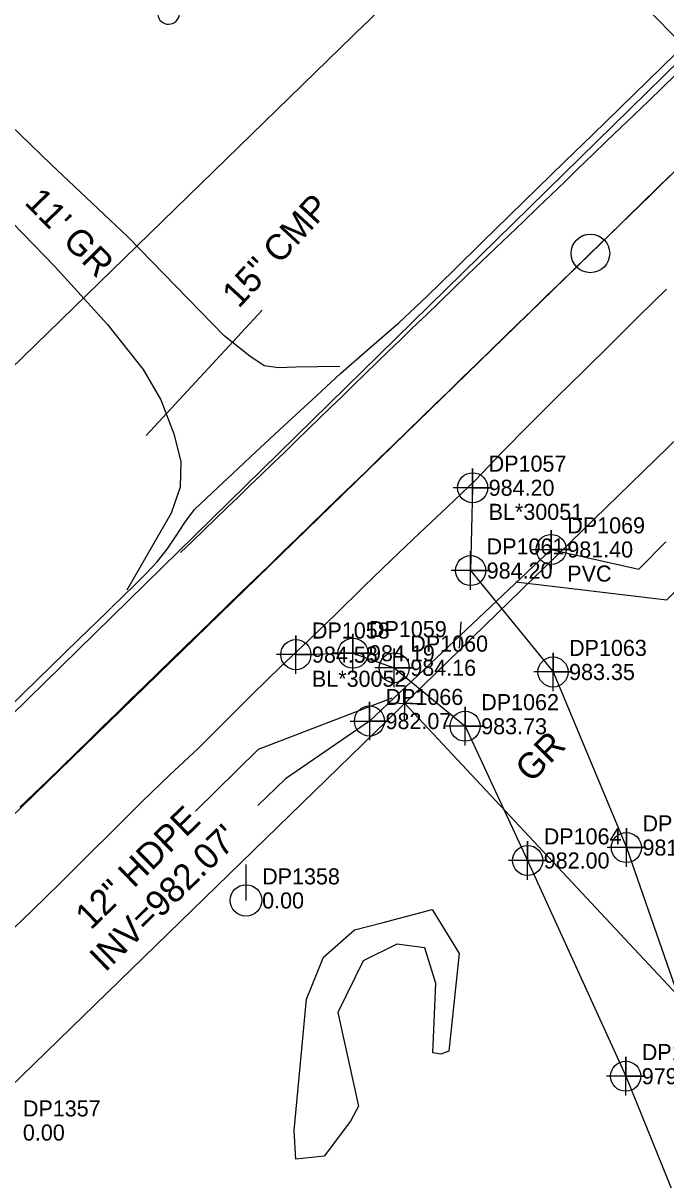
# Model space of a CAD drawing. Extents: x 1182322 to 1186765, y 572295 to 575411.
# Drawn here: x 1184975.7 to 1185075.6, y 574526.7 to 574706.6 of the extents above; entities that cross this region are included whole.
import ezdxf

# ---------------------------------------------------------------- set-up
doc = ezdxf.new("R2010")
doc.units = 0
for name, color, linetype in [('COGO Default Chain', 7, 'Continuous'), ('Exist Horizontal Alignment', 7, 'Continuous'), ('Exist Horizontal Alignment Point', 7, 'Continuous'), ('Exist Property Corner CELL', 7, 'Continuous'), ('Exist Property Line', 7, 'Continuous'), ('Exist Right of Way Line', 7, 'Continuous'), ('Exist Right of Way Width CELL', 7, 'Continuous'), ('Exist Roads EOP', 7, 'Continuous'), ('Exist Roads EOT', 7, 'Continuous'), ('Exist Roads Soil', 7, 'Continuous'), ('Exist Roads Soil Cogo Comment', 7, 'Continuous'), ('Exist Roads Soil Cogo Elevation', 7, 'Continuous'), ('Exist Roads Soil Cogo Number', 7, 'Continuous'), ('Exist Roads Soil Cogo Point CELL', 7, 'Continuous'), ('Exist Roads Soil Text', 7, 'Continuous'), ('Exist Structure Minor Pipes CMP 15 Inch', 7, 'Continuous'), ('Exist Structure Minor Pipes CMP 15 Inch Text', 7, 'Continuous'), ('Exist Structure Minor Pipes HDPE 12 Inch', 7, 'Continuous'), ('Exist Structure Minor Pipes HDPE 12 Inch Cogo Comment', 7, 'Continuous'), ('Exist Structure Minor Pipes HDPE 12 Inch Cogo Elevation', 7, 'Continuous'), ('Exist Structure Minor Pipes HDPE 12 Inch Cogo Number', 7, 'Continuous'), ('Exist Structure Minor Pipes HDPE 12 Inch Cogo Point CELL', 7, 'Continuous'), ('Exist Structure Minor Pipes HDPE 12 Inch Invert', 7, 'Continuous'), ('Exist Structure Minor Pipes HDPE 12 Inch Text', 7, 'Continuous'), ('Exist Structure Minor Pipes RCP 24 Inch Invert', 7, 'Continuous'), ('Exist Utilities Power Pole CELL', 7, 'Continuous'), ('Exist Utilities Power Pole Cogo Elevation', 7, 'Continuous'), ('Exist Utilities Power Pole Cogo Number', 7, 'Continuous'), ('Exist Utilities Water UG Line SUE LOS C', 7, 'Continuous'), ('Exist Vegetation Tree CELL', 7, 'Continuous'), ('Exist Vegetation Woods Line', 7, 'Continuous')]:
    doc.layers.add(name, color=color, linetype=linetype)

msp = doc.modelspace()

# ---------------------------------------------------------------- linework, layer by layer
at = {"layer": 'COGO Default Chain'}
msp.add_line((1184906.77, 574517.85), (1185063.9, 574670.82), dxfattribs=at)
msp.add_arc((1211496.85, 547519.36), 37893.3, 134.022628, 134.231777, dxfattribs=at)
at = {"layer": 'Exist Horizontal Alignment'}
msp.add_line((1184906.77, 574517.85), (1185063.9, 574670.82), dxfattribs=at)
msp.add_arc((1211496.85, 547519.36), 37893.3, 134.022628, 134.231777, dxfattribs=at)
at = {"layer": 'Exist Horizontal Alignment Point'}
msp.add_circle((1185063.9, 574670.82), 3, dxfattribs=at)
at = {"layer": 'Exist Property Corner CELL'}
msp.add_line((1185035.03, 574600.84), (1185035.03, 574600.84), dxfattribs=at)
msp.add_lwpolyline([(1185032.53, 574600.92), (1185037.53, 574600.75), (1185035.03, 574600.84), (1185035.11, 574603.34), (1185034.94, 574598.34)], dxfattribs=at)
at = {"layer": 'Exist Property Line'}
msp.add_line((1185035.03, 574600.84), (1185095.5, 574536.04), dxfattribs=at)
at = {"layer": 'Exist Right of Way Line'}
for p, q in [((1184871.9, 574553.67), (1185029.02, 574706.64)), ((1184927.7, 574496.35), (1185084.83, 574649.32))]:
    msp.add_line(p, q, dxfattribs=at)
msp.add_arc((1211496.85, 547519.36), 37943.3, 134.022628, 134.231777, dxfattribs=at)
at = {"layer": 'Exist Right of Way Width CELL'}
msp.add_line((1185087.47, 574693.74), (1185065.48, 574716.36), dxfattribs=at)
at = {"layer": 'Exist Roads EOP'}
for points in [[(1185007.48, 574635.8), (1185011.87, 574639.89), (1185016.26, 574643.98), (1185020.65, 574648.07), (1185025.06, 574652.14), (1185029.56, 574656.1), (1185034.11, 574660.02), (1185038.5, 574664.11), (1185042.79, 574668.3), (1185047.04, 574672.53), (1185051.32, 574676.73), (1185055.62, 574680.92), (1185059.92, 574685.1), (1185064.22, 574689.29), (1185068.51, 574693.48), (1185072.81, 574697.66), (1185077.11, 574701.85)], [(1185075.72, 574665.26), (1185071.45, 574661.05), (1185067.18, 574656.83), (1185062.91, 574652.62), (1185058.64, 574648.4), (1185054.38, 574644.18), (1185050.19, 574639.89), (1185046.03, 574635.56), (1185041.7, 574631.41), (1185037.34, 574627.29), (1185032.97, 574623.18), (1185028.66, 574619.01), (1185024.41, 574614.77), (1185020.06, 574610.63), (1185015.72, 574606.49), (1185011.43, 574602.3), (1185007.18, 574598.06), (1185002.93, 574593.83), (1184998.55, 574589.73), (1184994.24, 574585.55), (1184989.99, 574581.33), (1184985.73, 574577.1), (1184981.48, 574572.86), (1184977.18, 574568.68), (1184972.87, 574564.5)], [(1184989.5, 574615.78), (1184991.29, 574617.52), (1184993.08, 574619.27), (1184994.87, 574621.01), (1184996.58, 574622.84), (1184998.1, 574624.82), (1184999.54, 574626.87), (1185000.85, 574628.99), (1185002.35, 574631), (1185004.17, 574632.71), (1185006, 574634.41), (1185007.48, 574635.8)], [(1184893.98, 574523.02), (1184898.26, 574527.23), (1184902.55, 574531.42), (1184906.85, 574535.61), (1184911.15, 574539.79), (1184915.45, 574543.98), (1184919.74, 574548.16), (1184924.05, 574552.34), (1184928.36, 574556.52), (1184932.67, 574560.69), (1184936.97, 574564.87), (1184941.28, 574569.04), (1184945.61, 574573.2), (1184949.94, 574577.35), (1184954.28, 574581.5), (1184958.61, 574585.65), (1184962.92, 574589.83), (1184967.19, 574594.03), (1184971.47, 574598.24), (1184975.77, 574602.43), (1184980.07, 574606.61), (1184984.37, 574610.8), (1184988.67, 574614.98), (1184989.48, 574615.76)]]:
    msp.add_lwpolyline(points, dxfattribs=at)
at = {"layer": 'Exist Roads EOT'}
for points in [[(1185038.35, 574661.22), (1185040.5, 574663.31), (1185042.66, 574665.4), (1185044.81, 574667.48), (1185046.98, 574669.55), (1185049.16, 574671.62), (1185051.33, 574673.69), (1185053.49, 574675.77), (1185055.65, 574677.85), (1185057.81, 574679.93), (1185059.97, 574682.02), (1185062.12, 574684.11), (1185064.26, 574686.21), (1185066.42, 574688.29), (1185068.58, 574690.37), (1185070.75, 574692.44), (1185072.92, 574694.52), (1185075.08, 574696.6), (1185077.24, 574698.68)], [(1185076.31, 574682.96), (1185074.17, 574680.86), (1185072.02, 574678.76), (1185069.88, 574676.66), (1185067.74, 574674.56), (1185065.59, 574672.47), (1185063.44, 574670.38), (1185061.29, 574668.29), (1185059.13, 574666.2), (1185056.98, 574664.11), (1185054.83, 574662.02), (1185052.68, 574659.93), (1185050.53, 574657.83), (1185048.39, 574655.74), (1185046.24, 574653.65), (1185044.09, 574651.55), (1185041.94, 574649.46), (1185039.79, 574647.37), (1185037.64, 574645.28), (1185035.49, 574643.19), (1185033.33, 574641.1), (1185031.18, 574639.01), (1185029.03, 574636.92), (1185026.87, 574634.83), (1185024.72, 574632.74), (1185022.57, 574630.65), (1185020.42, 574628.57), (1185018.26, 574626.48), (1185016.11, 574624.39), (1185013.95, 574622.3), (1185011.8, 574620.21), (1185009.64, 574618.13), (1185007.49, 574616.04), (1185005.33, 574613.95), (1185003.18, 574611.87), (1185001.02, 574609.78), (1184998.87, 574607.69), (1184996.72, 574605.6), (1184994.57, 574603.51), (1184992.42, 574601.41), (1184990.28, 574599.31), (1184988.14, 574597.21), (1184986, 574595.11), (1184983.85, 574593.02), (1184981.7, 574590.93), (1184979.55, 574588.84), (1184977.39, 574586.75), (1184975.24, 574584.66)], [(1185000.2, 574624.29), (1185002.01, 574626.02), (1185003.8, 574627.76), (1185005.6, 574629.5), (1185007.39, 574631.24), (1185009.19, 574632.98), (1185010.99, 574634.71), (1185012.79, 574636.45), (1185014.59, 574638.18), (1185016.38, 574639.92), (1185018.18, 574641.66), (1185019.97, 574643.41), (1185021.76, 574645.15), (1185023.55, 574646.89), (1185025.35, 574648.64), (1185027.14, 574650.38), (1185028.93, 574652.12), (1185030.72, 574653.86), (1185032.52, 574655.6), (1185034.32, 574657.33), (1185036.12, 574659.07), (1185037.92, 574660.81), (1185038.35, 574661.22)]]:
    msp.add_lwpolyline(points, dxfattribs=at)
at = {"layer": 'Exist Roads Soil'}
for points in [[(1184864.18, 574782.1), (1184871.91, 574781.1), (1184874.14, 574780.41), (1184878.92, 574775.51), (1184891.68, 574760.82), (1184894.88, 574763.09), (1184906.71, 574747.55), (1184918.92, 574732.26), (1184921.31, 574729.41), (1184928.86, 574720.61), (1184938.62, 574709.66), (1184952.69, 574695.85), (1184962.57, 574686.5), (1184970.7, 574678.99), (1184980.59, 574668.85), (1184988.85, 574659.76), (1184994.38, 574652.74), (1184997.14, 574648.04), (1184999.15, 574642.75), (1185000.26, 574638.43), (1185000.13, 574634.44), (1184998.74, 574630.44), (1184991.86, 574618.44)], [(1185024.93, 574653.25), (1185018.14, 574653.11), (1185015.44, 574653), (1185013.2, 574653.35), (1185010.97, 574654.83), (1185007, 574658.01), (1184992.01, 574673.39), (1184980.01, 574684.7), (1184970.55, 574693.85), (1184955.63, 574707.58), (1184943.26, 574719.16), (1184932.76, 574729.39), (1184925.07, 574737.84), (1184915.67, 574749.91), (1184905.1, 574765.3), (1184902.54, 574769.17), (1184917.01, 574781.63)], [(1185045.59, 574634.37), (1185045.28, 574621.49), (1185058.09, 574605.71), (1185069.5, 574578.4), (1185082.05, 574542.31), (1185102.37, 574503.96), (1185117.61, 574482.76), (1185142.22, 574457.07), (1185176.6, 574433.19), (1185216.79, 574411.03), (1185238.15, 574406.65)], [(1185018.12, 574608.41), (1185026.99, 574608.63), (1185033.41, 574606.37), (1185044.43, 574597.27), (1185054.15, 574576.39), (1185069.39, 574542.83), (1185084.04, 574506.75), (1185105.39, 574472.96), (1185128.38, 574447.83), (1185159.03, 574420.36), (1185190.93, 574393.48), (1185218.16, 574375.85)]]:
    msp.add_lwpolyline(points, dxfattribs=at)
at = {"layer": 'Exist Roads Soil Cogo Point CELL'}
for points in [[(1185045.59, 574631.37), (1185045.59, 574637.37), (1185045.59, 574634.37), (1185048.59, 574634.37), (1185042.59, 574634.37)], [(1185045.28, 574618.49), (1185045.28, 574624.49), (1185045.28, 574621.49), (1185048.28, 574621.49), (1185042.28, 574621.49)], [(1185018.12, 574605.41), (1185018.12, 574611.41), (1185018.12, 574608.41), (1185021.12, 574608.41), (1185015.12, 574608.41)], [(1185026.99, 574605.63), (1185026.99, 574611.63), (1185026.99, 574608.63), (1185029.99, 574608.63), (1185023.99, 574608.63)], [(1185033.41, 574603.37), (1185033.41, 574609.37), (1185033.41, 574606.37), (1185036.41, 574606.37), (1185030.41, 574606.37)], [(1185058.09, 574602.71), (1185058.09, 574608.71), (1185058.09, 574605.71), (1185061.09, 574605.71), (1185055.09, 574605.71)], [(1185044.43, 574594.27), (1185044.43, 574600.27), (1185044.43, 574597.27), (1185047.43, 574597.27), (1185041.43, 574597.27)], [(1185069.5, 574575.4), (1185069.5, 574581.4), (1185069.5, 574578.4), (1185072.5, 574578.4), (1185066.5, 574578.4)], [(1185054.15, 574573.39), (1185054.15, 574579.39), (1185054.15, 574576.39), (1185057.15, 574576.39), (1185051.15, 574576.39)], [(1185069.39, 574539.83), (1185069.39, 574545.83), (1185069.39, 574542.83), (1185072.39, 574542.83), (1185066.39, 574542.83)]]:
    msp.add_lwpolyline(points, dxfattribs=at)
for centre in [(1185045.59, 574634.37), (1185045.28, 574621.49), (1185018.12, 574608.41), (1185026.99, 574608.63), (1185033.41, 574606.37), (1185058.09, 574605.71), (1185044.43, 574597.27), (1185069.5, 574578.4), (1185054.15, 574576.39), (1185069.39, 574542.83)]:
    msp.add_circle(centre, 2.34, dxfattribs=at)
at = {"layer": 'Exist Structure Minor Pipes CMP 15 Inch'}
msp.add_line((1184994.84, 574642.48), (1185012.89, 574662.01), dxfattribs=at)
at = {"layer": 'Exist Structure Minor Pipes HDPE 12 Inch'}
for p, q in [((1185043.69, 574611.42), (1185057.81, 574624.77)), ((1185029.56, 574598.08), (1185043.69, 574611.42))]:
    msp.add_line(p, q, dxfattribs=at)
at = {"layer": 'Exist Structure Minor Pipes HDPE 12 Inch Cogo Point CELL'}
for points in [[(1185054.81, 574624.77), (1185060.81, 574624.77), (1185057.81, 574624.77), (1185057.81, 574627.77), (1185057.81, 574621.77)], [(1185026.56, 574598.08), (1185032.56, 574598.08), (1185029.56, 574598.08), (1185029.56, 574601.08), (1185029.56, 574595.08)]]:
    msp.add_lwpolyline(points, dxfattribs=at)
for centre in [(1185057.81, 574624.77), (1185029.56, 574598.08)]:
    msp.add_circle(centre, 2.34, dxfattribs=at)
at = {"layer": 'Exist Structure Minor Pipes HDPE 12 Inch Text'}
msp.add_line((1185043.57, 574609.44), (1185043.81, 574613.5), dxfattribs=at)
at = {"layer": 'Exist Structure Minor Pipes RCP 24 Inch Invert'}
for points in [[(1185057.81, 574624.77), (1185071.42, 574621.68), (1185075.61, 574625.97)], [(1185052.33, 574619.72), (1185075.77, 574616.92), (1185083.19, 574624.53)], [(1185033.05, 574601.65), (1185012.27, 574593.67), (1185002.54, 574584.04)], [(1185029.56, 574598.08), (1185016.49, 574589.11), (1185012.2, 574584.92)]]:
    msp.add_lwpolyline(points, dxfattribs=at)
at = {"layer": 'Exist Utilities Power Pole CELL'}
for q in [(1185010.38, 574575.79), (1185010.38, 574570.17)]:
    msp.add_line((1185010.38, 574570.17), q, dxfattribs=at)
msp.add_circle((1185010.38, 574570.17), 2.45, dxfattribs=at)
at = {"layer": 'Exist Utilities Water UG Line SUE LOS C'}
msp.add_lwpolyline([(1184698.37, 574456.58), (1184835.97, 574463.78), (1185103.91, 574726.55), (1185431.28, 575046.78)], dxfattribs=at)
at = {"layer": 'Exist Vegetation Tree CELL'}
msp.add_arc((1184998.33, 574708.17), 1.69, 111.5671, 6.231, dxfattribs=at)
at = {"layer": 'Exist Vegetation Woods Line'}
msp.add_lwpolyline([(1185017.87, 574534.4), (1185019.78, 574554.83), (1185022.4, 574561.35), (1185027.25, 574565.6), (1185031.7, 574566.74), (1185039.3, 574568.79), (1185043.48, 574561.94), (1185041.9, 574546.72), (1185040.65, 574546.25), (1185039.43, 574546.45), (1185039.89, 574557.24), (1185038.18, 574562.78), (1185033.84, 574563.39), (1185028.58, 574560.79), (1185024.63, 574552.73), (1185027.84, 574538.17), (1185026.63, 574535.85), (1185022.51, 574530.41), (1185018.09, 574529.94), (1185017.87, 574534.4)], dxfattribs=at)

# ---------------------------------------------------------------- texts
at = {"layer": 'Exist Roads Soil Cogo Comment'}
for s, p in [('BL*30051', (1185048.09, 574629.37)), ('BL*30052', (1185020.62, 574603.41))]:
    msp.add_text(s, height=2.5, dxfattribs=at).set_placement(p)
at = {"layer": 'Exist Roads Soil Cogo Elevation'}
for s, p in [('984.20', (1185048.09, 574633.12)), ('984.20', (1185047.78, 574620.24)), ('984.58', (1185020.62, 574607.16)), ('984.19', (1185029.49, 574607.38)), ('984.16', (1185035.91, 574605.12)), ('983.35', (1185060.59, 574604.46)), ('983.73', (1185046.93, 574596.02)), ('981.16', (1185072, 574577.15)), ('982.00', (1185056.65, 574575.14)), ('979.09', (1185071.89, 574541.58))]:
    msp.add_text(s, height=2.5, dxfattribs=at).set_placement(p)
at = {"layer": 'Exist Roads Soil Cogo Number'}
for s, p in [('DP1057', (1185048.09, 574636.87)), ('DP1061', (1185047.78, 574623.99)), ('DP1058', (1185020.62, 574610.91)), ('DP1059', (1185029.49, 574611.13)), ('DP1060', (1185035.91, 574608.87)), ('DP1063', (1185060.59, 574608.21)), ('DP1062', (1185046.93, 574599.77)), ('DP1065', (1185072, 574580.9)), ('DP1064', (1185056.65, 574578.89)), ('DP1067', (1185071.89, 574545.33))]:
    msp.add_text(s, height=2.5, dxfattribs=at).set_placement(p)
at = {"layer": 'Exist Roads Soil Text'}
for s, rotation, p in [("11' GR", 314.2845, (1184975.8, 574678.63)), ('GR', 45.5166, (1185054.7, 574588.33))]:
    msp.add_text(s, height=4, rotation=rotation, dxfattribs=at).set_placement(p)
at = {"layer": 'Exist Structure Minor Pipes CMP 15 Inch Text'}
msp.add_text('15" CMP', height=4, rotation=47.2479, dxfattribs=at).set_placement((1185009.23, 574662.15))
at = {"layer": 'Exist Structure Minor Pipes HDPE 12 Inch Cogo Comment'}
msp.add_text('PVC', height=2.5, dxfattribs=at).set_placement((1185060.31, 574619.77))
at = {"layer": 'Exist Structure Minor Pipes HDPE 12 Inch Cogo Elevation'}
for s, p in [('981.40', (1185060.31, 574623.52)), ('982.07', (1185032.06, 574596.83))]:
    msp.add_text(s, height=2.5, dxfattribs=at).set_placement(p)
at = {"layer": 'Exist Structure Minor Pipes HDPE 12 Inch Cogo Number'}
for s, p in [('DP1069', (1185060.31, 574627.27)), ('DP1066', (1185032.06, 574600.58))]:
    msp.add_text(s, height=2.5, dxfattribs=at).set_placement(p)
at = {"layer": 'Exist Structure Minor Pipes HDPE 12 Inch Invert'}
msp.add_text("INV=982.07'", height=4, rotation=44.3666, dxfattribs=at).set_placement((1184988.48, 574558.92))
at = {"layer": 'Exist Structure Minor Pipes HDPE 12 Inch Text'}
msp.add_text('12" HDPE', height=4, rotation=44.3202, dxfattribs=at).set_placement((1184986.24, 574565.45))
at = {"layer": 'Exist Utilities Power Pole Cogo Elevation'}
for p in [(1185012.88, 574568.92), (1184975.69, 574532.82)]:
    msp.add_text('0.00', height=2.5, dxfattribs=at).set_placement(p)
at = {"layer": 'Exist Utilities Power Pole Cogo Number'}
for s, p in [('DP1358', (1185012.88, 574572.67)), ('DP1357', (1184975.69, 574536.57))]:
    msp.add_text(s, height=2.5, dxfattribs=at).set_placement(p)

doc.saveas('drawing.dxf')
